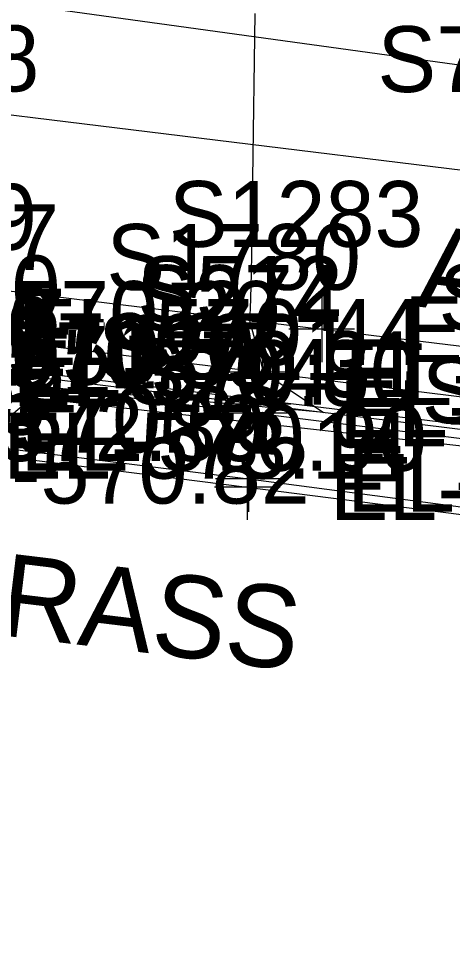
# Model space of a CAD drawing. Extents: x 1724534 to 1727318, y 657156 to 660047.
# Drawn here: x 1725799.8 to 1725826.2, y 658512.1 to 658568.3 of the extents above; entities that cross this region are included whole.
import ezdxf

# ---------------------------------------------------------------- set-up
doc = ezdxf.new("R2010")
doc.units = 0
for name, color, linetype in [('SURVEY - CONTOURS - Intermediate with optional Text', 7, 'Continuous'), ('SURVEY - DRAINAGE - Area Shapes', 7, 'Continuous'), ('SURVEY - DRAINAGE - Storm Sewer', 7, 'Continuous'), ('SURVEY - DTM - Breaklines', 7, 'Continuous'), ('SURVEY - DTM - Breaklines - Points - Elevations', 7, 'Continuous'), ('SURVEY - DTM - Breaklines - Points - Locators', 7, 'Continuous'), ('SURVEY - DTM - Breaklines - Points - Numbers', 7, 'Continuous'), ('SURVEY - ROADSIDE BARRIERS - Points - Elevations', 7, 'Continuous'), ('SURVEY - ROADSIDE BARRIERS - Points - Locators', 7, 'Continuous'), ('SURVEY - ROADSIDE BARRIERS - Points - Numbers', 7, 'Continuous'), ('SURVEY - ROADSIDE BARRIERS with Text', 7, 'Continuous'), ('SURVEY - TRAFFIC CONTROL - Pavement Marking - Points - Elevations', 7, 'Continuous'), ('SURVEY - TRAFFIC CONTROL - Pavement Marking - Points - Numbers', 7, 'Continuous'), ('SURVEY - TRAFFIC CONTROL - Pavement Marking with Text', 7, 'Continuous'), ('SURVEY - TRANSPORTATION - Features', 7, 'Continuous'), ('SURVEY - TRANSPORTATION - Features - Points - Elevations', 7, 'Continuous'), ('SURVEY - TRANSPORTATION - Features - Points - Locators', 7, 'Continuous'), ('SURVEY - TRANSPORTATION - Features - Points - Numbers', 7, 'Continuous'), ('SURVEY - TRANSPORTATION - Features Text', 7, 'Continuous'), ('SURVEY - TRANSPORTATION - Roads', 7, 'Continuous'), ('SURVEY - TRANSPORTATION - Roads - Points - Elevations', 7, 'Continuous'), ('SURVEY - TRANSPORTATION - Roads - Points - Locators', 7, 'Continuous'), ('SURVEY - TRANSPORTATION - Roads - Points - Numbers', 7, 'Continuous'), ('SURVEY - UTILITIES - Electric (Lighting) - Points - Elevations', 7, 'Continuous'), ('SURVEY - UTILITIES - Electric (Lighting) - Points - Numbers', 7, 'Continuous'), ('SURVEY - UTILITIES - Electric (Underground) with Text', 7, 'Continuous'), ('SURVEY - UTILITIES - Poles and Miscellaneous - Points - Elevations', 7, 'Continuous'), ('SURVEY - VEGETATION - Features with Text', 7, 'Continuous')]:
    doc.layers.add(name, color=color, linetype=linetype)

msp = doc.modelspace()

# ---------------------------------------------------------------- linework, layer by layer
at = {"layer": 'SURVEY - CONTOURS - Intermediate with optional Text'}
msp.add_lwpolyline([(1725814.216, 658568.57), (1725814.066, 658558.51), (1725814.016, 658555.189), (1725813.977, 658552.773), (1725813.95, 658551.26), (1725813.934, 658550.652), (1725813.888, 658549.921), (1725814.464, 658547.762), (1725814.572, 658547.357), (1725814.649, 658547.068), (1725814.696, 658546.894), (1725814.711, 658546.836), (1725814.711, 658546.835), (1725814.712, 658546.831), (1725814.713, 658546.824), (1725814.714, 658546.814), (1725814.72, 658546.765), (1725814.988, 658546.587), (1725815.203, 658546.444), (1725815.538, 658546.222), (1725815.992, 658545.921), (1725818.388, 658544.331), (1725815.793, 658544.566), (1725815.452, 658544.597), (1725815.193, 658544.621), (1725815.016, 658544.637), (1725814.654, 658544.67), (1725814.45, 658544.689), (1725814.399, 658544.693), (1725814.382, 658544.695), (1725814.382, 658544.695), (1725814.382, 658544.695), (1725814.382, 658544.695), (1725814.382, 658544.695), (1725814.381, 658544.695), (1725814.326, 658544.7), (1725814.16, 658544.715), (1725813.496, 658544.775), (1725812.316, 658544.881), (1725811.891, 658544.92), (1725811.5, 658544.955), (1725811.144, 658544.987), (1725810.009, 658545.089), (1725809.709, 658545.117), (1725809.416, 658545.143), (1725809.131, 658545.169), (1725808.854, 658545.194), (1725807.827, 658545.286), (1725807.479, 658545.318), (1725807.08, 658545.354), (1725806.631, 658545.394), (1725805.367, 658545.509), (1725804.604, 658545.577), (1725804.361, 658545.599), (1725804.211, 658545.613), (1725803.935, 658545.638), (1725803.799, 658545.65), (1725803.341, 658545.692), (1725803.018, 658545.721), (1725801.363, 658545.87), (1725800.738, 658545.3), (1725800.596, 658545.172), (1725800.267, 658544.879), (1725800.078, 658544.715), (1725799.556, 658544.26)], dxfattribs=at)
at = {"layer": 'SURVEY - DRAINAGE - Area Shapes'}
msp.add_lwpolyline([(1725876.527, 658537.521), (1725880.453, 658568.253), (1725462.782, 658619.36), (1725459.014, 658588.567)], close=True, dxfattribs=at)
at = {"layer": 'SURVEY - DRAINAGE - Storm Sewer'}
msp.add_lwpolyline([(1725899.594, 658555.371), (1725464.565, 658615.304), (1725129.381, 658652.795)], dxfattribs=at)
at = {"layer": 'SURVEY - DTM - Breaklines'}
msp.add_lwpolyline([(1725680.682, 658560.757), (1725700.532, 658558.327), (1725720.383, 658555.896), (1725740.231, 658553.451), (1725761.261, 658550.794), (1725763.358, 658550.522), (1725772.397, 658549.361), (1725785.767, 658547.812), (1725794.485, 658546.715), (1725814.329, 658544.278), (1725834.171, 658541.836), (1725838.432, 658541.293), (1725858.267, 658538.797), (1725873.4, 658536.913), (1725878.358, 658536.288), (1725898.186, 658533.731), (1725916.254, 658531.264)], dxfattribs=at)
at = {"layer": 'SURVEY - DTM - Breaklines - Points - Locators'}
for p, q in [((1725814.329, 658546.278), (1725814.329, 658542.278)), ((1725816.329, 658544.278), (1725812.329, 658544.278))]:
    msp.add_line(p, q, dxfattribs=at)
at = {"layer": 'SURVEY - ROADSIDE BARRIERS - Points - Locators'}
for p, q in [((1725813.751, 658541.797), (1725813.751, 658537.797)), ((1725815.751, 658539.797), (1725811.751, 658539.797))]:
    msp.add_line(p, q, dxfattribs=at)
at = {"layer": 'SURVEY - ROADSIDE BARRIERS with Text'}
msp.add_lwpolyline([(1725760.694, 658546.317), (1725762.794, 658546.074), (1725771.84, 658544.972), (1725785.195, 658543.377), (1725793.917, 658542.307), (1725813.751, 658539.797), (1725833.582, 658537.268), (1725837.82, 658536.545)], dxfattribs=at)
at = {"layer": 'SURVEY - TRAFFIC CONTROL - Pavement Marking with Text'}
msp.add_lwpolyline([(1725507.893, 658598.435), (1725611.44, 658585.624), (1725663.045, 658579.239), (1725732.511, 658570.646), (1725771.433, 658565.831), (1725828.993, 658558.789), (1725876.604, 658552.91), (1725911.384, 658548.615)], dxfattribs=at)
at = {"layer": 'SURVEY - TRANSPORTATION - Features'}
for points in [[(1725680.75, 658561.297), (1725700.601, 658558.867), (1725720.452, 658556.439), (1725740.3, 658553.994), (1725761.33, 658551.338), (1725763.427, 658551.066), (1725772.465, 658549.905), (1725773.017, 658549.841), (1725785.837, 658548.356), (1725794.555, 658547.258), (1725814.399, 658544.822), (1725834.241, 658542.379), (1725838.502, 658541.836), (1725858.338, 658539.34), (1725873.47, 658537.457), (1725878.428, 658536.831), (1725898.256, 658534.275), (1725916.324, 658531.808)], [(1725773.017, 658549.841), (1725772.713, 658551.857), (1725786.089, 658550.308), (1725794.807, 658549.211), (1725814.651, 658546.773), (1725834.493, 658544.331), (1725838.754, 658543.788), (1725858.589, 658541.292), (1725873.721, 658539.408), (1725878.681, 658538.783), (1725898.508, 658536.226), (1725916.581, 658533.801)], [(1725760.676, 658546.181), (1725762.959, 658547.374), (1725771.996, 658546.202), (1725785.261, 658543.884), (1725793.979, 658542.787), (1725813.816, 658540.298), (1725833.635, 658537.675), (1725837.876, 658536.979), (1725857.711, 658534.482), (1725872.844, 658532.599), (1725877.802, 658531.973), (1725897.627, 658529.389), (1725915.695, 658526.927)]]:
    msp.add_lwpolyline(points, dxfattribs=at)
at = {"layer": 'SURVEY - TRANSPORTATION - Features - Points - Locators'}
for p, q in [((1725814.651, 658548.773), (1725814.651, 658544.773)), ((1725816.651, 658546.773), (1725812.651, 658546.773)), ((1725814.399, 658546.822), (1725814.399, 658542.822)), ((1725816.399, 658544.822), (1725812.399, 658544.822)), ((1725813.816, 658542.298), (1725813.816, 658538.298)), ((1725815.816, 658540.298), (1725811.816, 658540.298))]:
    msp.add_line(p, q, dxfattribs=at)
at = {"layer": 'SURVEY - TRANSPORTATION - Roads'}
msp.add_lwpolyline([(1725616.971, 658574.343), (1725730.092, 658560.27), (1725772.626, 658554.978), (1725818.273, 658549.383), (1725869.87, 658543.106), (1725897.655, 658539.757), (1725899.639, 658539.517), (1725928.541, 658535.917)], dxfattribs=at)
at = {"layer": 'SURVEY - TRANSPORTATION - Roads - Points - Locators'}
for p, q in [((1725818.273, 658551.383), (1725818.273, 658547.383)), ((1725820.273, 658549.383), (1725816.273, 658549.383))]:
    msp.add_line(p, q, dxfattribs=at)
at = {"layer": 'SURVEY - UTILITIES - Electric (Underground) with Text'}
msp.add_lwpolyline([(1725780.974, 658547.452), (1725837.588, 658541.08), (1725892.762, 658533.99), (1725944.681, 658527.231), (1725958.361, 658525.297), (1725964.566, 658523.411), (1725971.45, 658518.072), (1725975.975, 658512.132)], dxfattribs=at)

# ---------------------------------------------------------------- texts
at = {"layer": 'SURVEY - DTM - Breaklines - Points - Elevations'}
for s, p in [('EL-570.30', (1725777.397, 658547.361)), ('EL-570.55', (1725790.767, 658545.812)), ('EL-570.80', (1725799.485, 658544.715)), ('EL-571.38', (1725819.329, 658542.278))]:
    msp.add_text(s, height=4, dxfattribs=at).set_placement(p)
at = {"layer": 'SURVEY - DTM - Breaklines - Points - Numbers'}
msp.add_text('S274', height=4, dxfattribs=at).set_placement((1725806.993, 658549.278))
at = {"layer": 'SURVEY - ROADSIDE BARRIERS - Points - Elevations'}
for s, p in [('EL-572.65', (1725776.84, 658542.972)), ('EL-572.89', (1725790.195, 658541.377)), ('EL-573.14', (1725798.917, 658540.307)), ('EL-573.64', (1725818.751, 658537.797))]:
    msp.add_text(s, height=4, dxfattribs=at).set_placement(p)
at = {"layer": 'SURVEY - ROADSIDE BARRIERS - Points - Numbers'}
msp.add_text('S704', height=4, dxfattribs=at).set_placement((1725806.415, 658544.797))
at = {"layer": 'SURVEY - TRAFFIC CONTROL - Pavement Marking - Points - Elevations'}
msp.add_text('EL-570.08', height=4, dxfattribs=at).set_placement((1725776.433, 658563.831))
at = {"layer": 'SURVEY - TRAFFIC CONTROL - Pavement Marking - Points - Numbers'}
msp.add_text('S767', height=4, dxfattribs=at).set_placement((1725821.657, 658563.789))
at = {"layer": 'SURVEY - TRANSPORTATION - Features - Points - Elevations'}
for s, p in [('EL-569.90', (1725777.713, 658549.857)), ('EL-570.20', (1725791.089, 658548.308)), ('EL-569.86', (1725777.465, 658547.905)), ('EL-569.87', (1725778.017, 658547.841)), ('EL-569.87', (1725778.017, 658547.841)), ('EL-570.44', (1725799.807, 658547.211)), ('EL-570.07', (1725790.837, 658546.356)), ('EL-570.31', (1725799.555, 658545.258)), ('EL-571.00', (1725819.651, 658544.773)), ('EL-570.39', (1725777.996, 658544.202)), ('EL-570.88', (1725819.399, 658542.822)), ('EL-570.68', (1725791.261, 658541.884)), ('EL-570.90', (1725799.979, 658540.787)), ('EL-571.47', (1725819.816, 658538.298))]:
    msp.add_text(s, height=4, dxfattribs=at).set_placement(p)
at = {"layer": 'SURVEY - TRANSPORTATION - Features - Points - Numbers'}
for s, p in [('S1779', (1725785.504, 658554.211)), ('S1780', (1725805.19, 658551.773)), ('S512', (1725807.063, 658549.822)), ('S1781', (1725825.363, 658549.331)), ('S2021', (1725804.686, 658546.298)), ('S2022', (1725824.347, 658543.675))]:
    msp.add_text(s, height=4, dxfattribs=at).set_placement(p)
at = {"layer": 'SURVEY - TRANSPORTATION - Features Text'}
msp.add_text('ASP.', height=5, rotation=352.8277, dxfattribs=at).set_placement((1725823.931, 658550.782))
at = {"layer": 'SURVEY - TRANSPORTATION - Roads - Points - Elevations'}
for s, p in [('EL-569.97', (1725777.626, 658552.978)), ('EL-571.11', (1725823.273, 658547.383))]:
    msp.add_text(s, height=4, dxfattribs=at).set_placement(p)
at = {"layer": 'SURVEY - TRANSPORTATION - Roads - Points - Numbers'}
msp.add_text('S1283', height=4, dxfattribs=at).set_placement((1725808.985, 658554.383))
at = {"layer": 'SURVEY - UTILITIES - Electric (Lighting) - Points - Elevations'}
msp.add_text('EL-570.82', height=4, dxfattribs=at).set_placement((1725792.864, 658538.793))
at = {"layer": 'SURVEY - UTILITIES - Electric (Lighting) - Points - Numbers'}
msp.add_text('S2071', height=4, dxfattribs=at).set_placement((1725792.864, 658545.793))
at = {"layer": 'SURVEY - UTILITIES - Poles and Miscellaneous - Points - Elevations'}
msp.add_text('EL-570.50', height=4, dxfattribs=at).set_placement((1725783.764, 658546.008))
at = {"layer": 'SURVEY - VEGETATION - Features with Text'}
msp.add_text('GRASS', height=5, rotation=353.1032, dxfattribs=at).set_placement((1725793.396, 658531.442))

doc.saveas('drawing.dxf')
